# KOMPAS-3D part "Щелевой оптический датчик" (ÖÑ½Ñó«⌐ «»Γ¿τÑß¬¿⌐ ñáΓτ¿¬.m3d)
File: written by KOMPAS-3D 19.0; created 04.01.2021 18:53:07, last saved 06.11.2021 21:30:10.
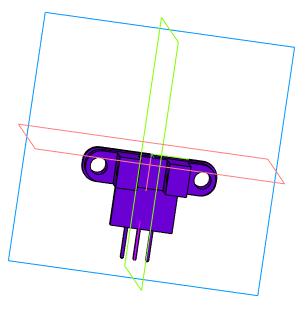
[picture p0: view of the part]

Document properties: Автор: Agent Smith; Организация: Pda-nn; Комментарий: Свободный софт !; Полное имя файла: D:\3D_print\3D проекты Компас 3D\Редуктор (Снова)\Щелевой оптический датчик.m3d

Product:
- Part/product: Щелевой оптический датчик
    Материал: Полиэтилен 20108-001 ГОСТ 16338-85 (density 949 kg/m3)
    Масса: 0.00128443

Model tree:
1. Эскиз:6
2. Элемент выдавливания:6
     Расстояние 1 = 1.8
3. Эскиз:7  (with: Элемент выдавливания:6)
4. Элемент выдавливания:7
     Расстояние 1 = 3.2
5. Эскиз:8  (with: Элемент выдавливания:7)
6. Элемент выдавливания:8
     Расстояние 1 = 8
7. Эскиз:9  (with: Элемент выдавливания:8)
8. Элемент выдавливания:9
9. Эскиз:10  (with: Элемент выдавливания:6)
10. Элемент выдавливания:10
     Расстояние 1 = 2.54
11. Эскиз:11  (with: Элемент выдавливания:6, Элемент выдавливания:9)
12. Элемент выдавливания:11
     Расстояние 1 = 1
13. Скругление:1  (with: Элемент выдавливания:11)
     Радиус = 0.5
14. Эскиз:12  (with: Элемент выдавливания:10)
15. Эскиз:13  (with: Элемент выдавливания:10)
16. Элемент по траектории:1
17. Фаска:1  (with: Элемент по траектории:1)
     Угол = 45; Длина 1 = 0.2; Длина 2 = 0.2
18. Массив по сетке:1  (with: Элемент по траектории:1)  (2 pattern instances)
     Наклон = 90; Шаг 1 = 2.54; Угол раствора = 90
19. Массив по сетке:2  (with: Элемент по траектории:1)  (2 pattern instances)
     Наклон = -90; Шаг 1 = 2.54; Угол раствора = 90
20. Фаска:2  (with: Элемент по траектории:1)  (labels: Полиэтилен 20108-001 ГОСТ 16338-85)
     Угол = 45; Длина 1 = 0.2; Длина 2 = 0.2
